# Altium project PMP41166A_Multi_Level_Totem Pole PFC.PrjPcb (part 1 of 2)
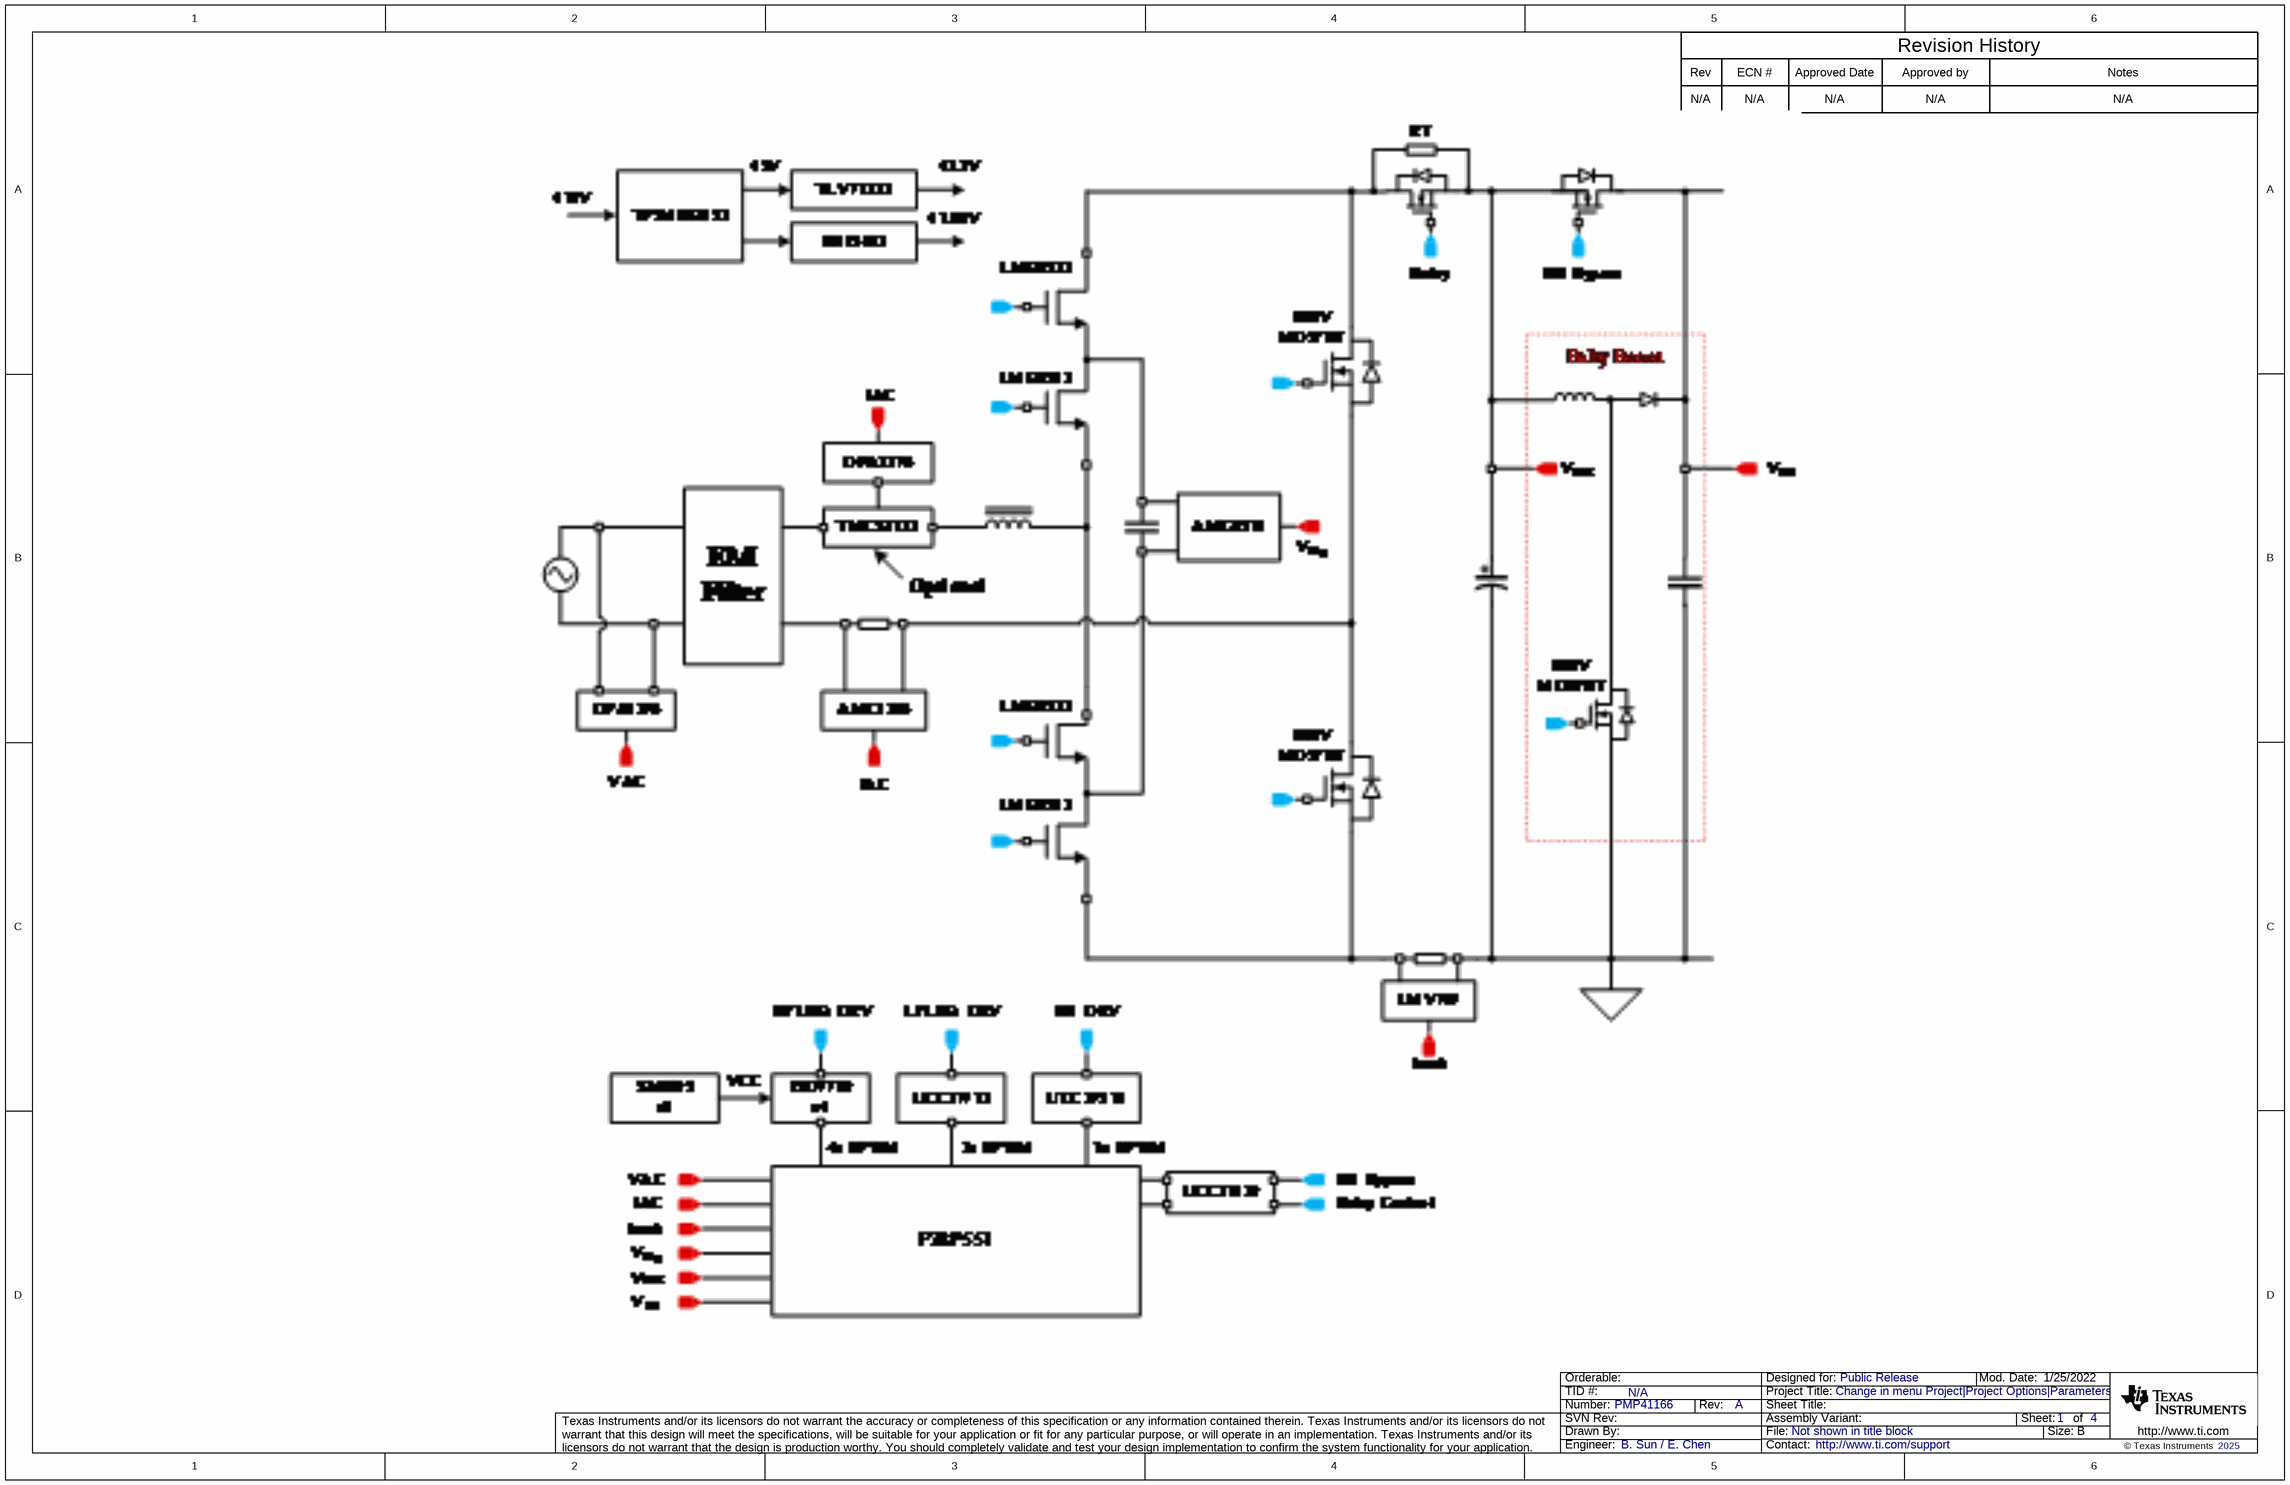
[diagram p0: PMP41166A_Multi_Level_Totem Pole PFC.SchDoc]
CopyrightYear: 2025; PCB_Layout: B. Sun / E. Chen; PCB_Rev: A; PRJ_Customer: Public Release; PRJ_Engineer: B. Sun / E. Chen; PRJ_Number: PMP41166; PRJ_Title: Change in menu Project|Project Options|Parameters; SCH_Rev: A; TechSupport: http://www.ti.com/support; TID: N/A
4 sheets, 262 parts. Net scope: flat (ports and power ports of the same name join across sheets).
Board file: PMP41166A_Multi_Level_Totem Pole PFC.PcbDoc
Sheets:
  PMP41166A_Multi_Level_Totem Pole PFC.SchDoc
  PMP41166A_Multi_Level_Totem Pole PFC_Main Board.SchDoc
  PMP41166A_Multi_Level_Totem Pole PFC_Control Card.SchDoc
  PMP41166A_Multi_Level_Totem Pole PFC_Hardware.SchDoc

## Sheet PMP41166A_Multi_Level_Totem Pole PFC.SchDoc
size 431 x 279 mm; Date: Not shown in title block; ApprovedBy: Not shown in title block; CheckedBy: Not shown in title block; Author: Not shown in title block; CompanyName: Not shown in title block; Engineer: Not shown in title block; Organization: Not shown in title block; Address1: Not shown in title block; Address2: Not shown in title block; Address3: Not shown in title block; Address4: Not shown in title block; DocumentNumber: 1; Revision: Use project parameter SCH_Rev; SheetNumber: 1; SheetTotal: 4; PageSetup: Record=PageOptions¦CenterHorizontal=True¦CenterVertical=True¦PrintScale=1.00¦XCorrection=1.00¦YCorrection=1.00¦PrintKind=0¦BorderSize=5000000¦LeftOffset=0¦BottomOffset=0¦Orientation=2¦PaperLength=1000¦PaperWidth=1000¦Scale=100¦PaperSource=15¦PrintQuality=600¦MediaType=1¦DitherType=10¦PaperKind=Letter¦PrintScaleMode=1

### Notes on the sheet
- Rev
- N/A
- ECN #
- Approved Date
- Approved by
- Revision History
- Notes

## Sheet PMP41166A_Multi_Level_Totem Pole PFC_Main Board.SchDoc
size A2; Date: Not shown in title block; ApprovedBy: Not shown in title block; CheckedBy: Not shown in title block; Author: Not shown in title block; CompanyName: Not shown in title block; Engineer: Not shown in title block; Organization: Not shown in title block; Address1: Not shown in title block; Address2: Not shown in title block; Address3: Not shown in title block; Address4: Not shown in title block; DocumentNumber: 1; Revision: Use project parameter SCH_Rev; SheetNumber: 2; SheetTotal: 4; PageSetup: Record=PageOptions¦CenterHorizontal=True¦CenterVertical=True¦PrintScale=0.69¦XCorrection=1.00¦YCorrection=1.00¦PrintKind=0¦BorderSize=5000000¦LeftOffset=0¦BottomOffset=0¦Orientation=2¦PaperLength=1000¦PaperWidth=1000¦Scale=100¦PaperSource=15¦PrintQuality=600¦MediaType=1¦DitherType=10¦PaperKind=Letter¦PrintScaleMode=1
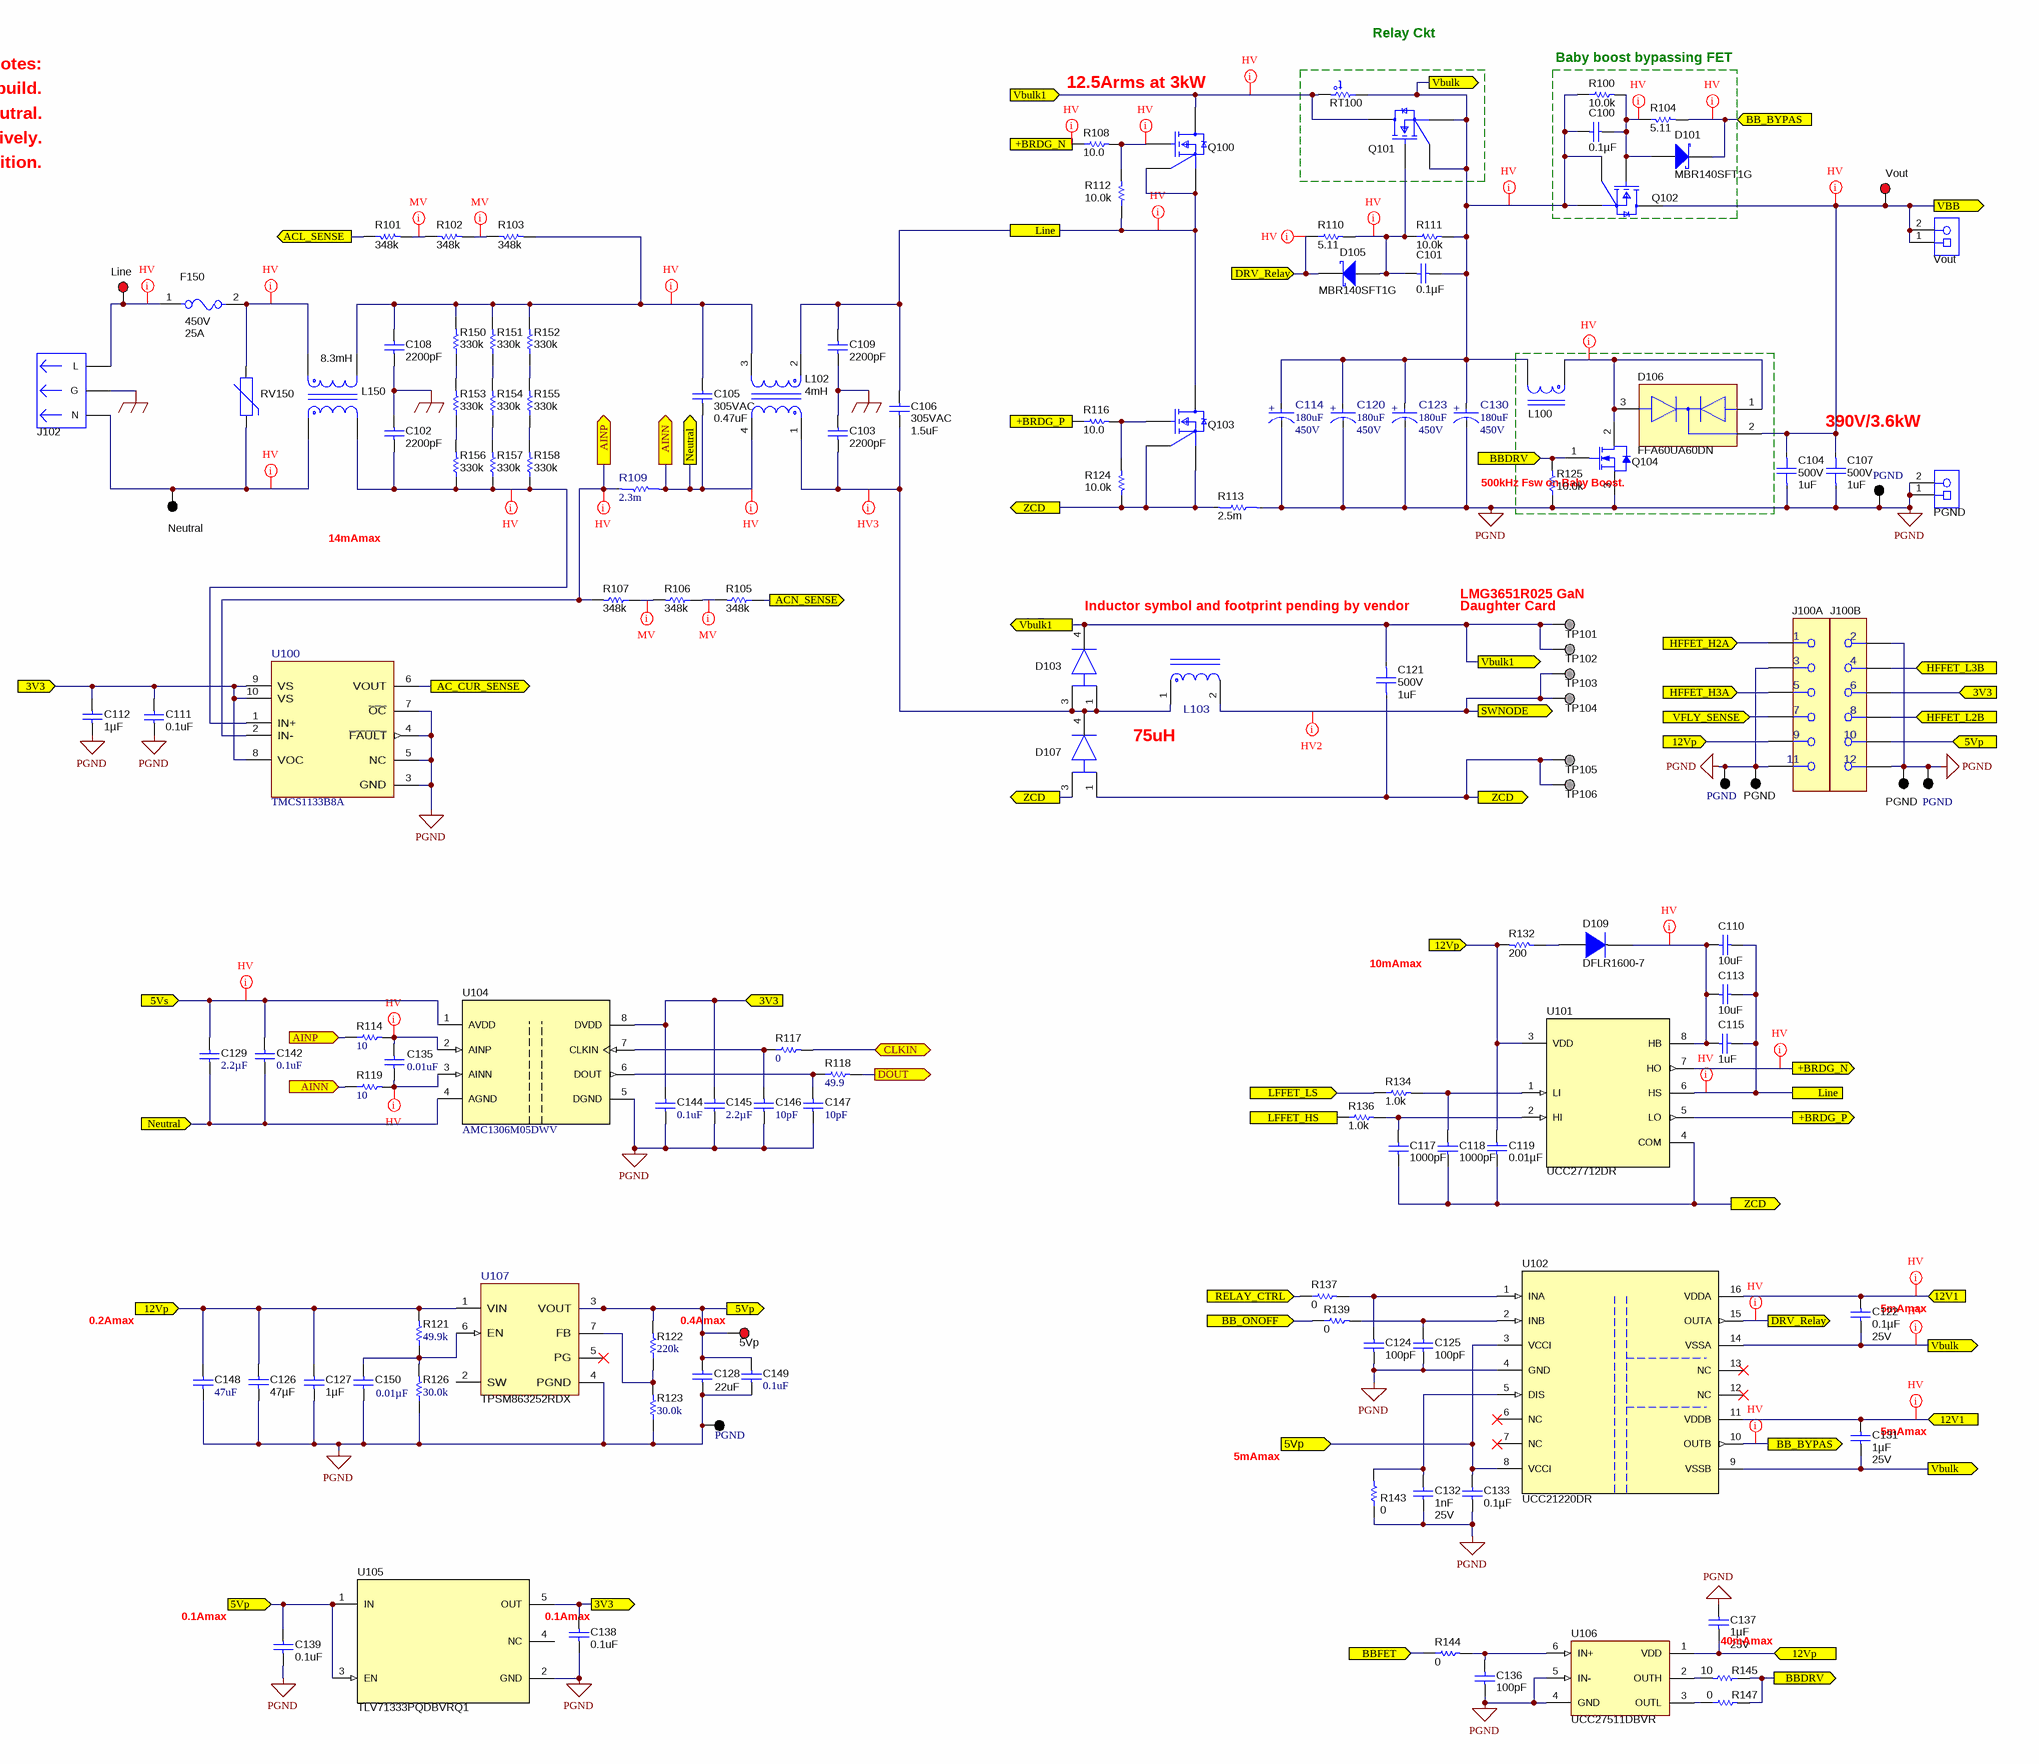
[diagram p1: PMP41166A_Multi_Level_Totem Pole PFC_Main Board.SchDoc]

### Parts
(Parts that share a designator on the sheet are numbered #1, #2 ... from top to bottom, then left to right.)
5Vp  5000  [Keystone5000]  (value not drawn)
C100  ValueDisplayed: 0.1µF  [0603]  (hidden comment: 06033C104JAT2A)
C101  ValueDisplayed: 0.1µF  [0603]  (hidden comment: 06033C104JAT2A)
C102  ValueDisplayed: 2200pF  [E_900x700x900]  (hidden comment: DE6E3KJ222MN3A)
C103  ValueDisplayed: 2200pF  [E_900x700x900]  (hidden comment: DE6E3KJ222MN3A)
C104  VDC_V: 500V  ValueDisplayed: 1uF  [FP-B58031U5105M062_SMD2-MFG]  (hidden comment: B58031U5105M062)
C105  Value2: 305VAC  ValueDisplayed: 0.47uF  [B32923_16.5mm_10.5]  (hidden comment: B32923H3474K000)
C106  Value2: 305VAC  ValueDisplayed: 1.5uF  [B32923_29.5mm]  (hidden comment: B32923H3155K000)
C107  VDC_V: 500V  ValueDisplayed: 1uF  [FP-B58031U5105M062_SMD2-MFG]  (hidden comment: B58031U5105M062)
C108  ValueDisplayed: 2200pF  [E_900x700x900]  (hidden comment: DE6E3KJ222MN3A)
C109  ValueDisplayed: 2200pF  [E_900x700x900]  (hidden comment: DE6E3KJ222MN3A)
C110  ValueDisplayed: 10uF  [0805_HV]  (hidden comment: 0805YD106MAT2A)
C111  ValueDisplayed: 0.1uF  [0402]  (hidden comment: GRM155R70J104KA01D)
C112  ValueDisplayed: 1µF  [0603]  (hidden comment: GRM185R60J105KE26D)
C113  ValueDisplayed: 10uF  [0805_HV]  (hidden comment: 0805YD106MAT2A)
C114  ValueDisplayed: 180uF  VDC_V: 450V  [FP-450HXW180MEFR16X50_RADIAL-MFG]  (hidden comment: 450HXW180MEFR16X50)
C115  ValueDisplayed: 1uF  [0603]  (hidden comment: C1608X7R1E105K080AB)
C117  ValueDisplayed: 1000pF  [0603]  (hidden comment: 06035A102KAT2A)
C118  ValueDisplayed: 1000pF  [0603]  (hidden comment: 06035A102KAT2A)
C119  ValueDisplayed: 0.01µF  [0603]  (hidden comment: C0603X103K5RACTU)
C120  ValueDisplayed: 180uF  VDC_V: 450V  [FP-450HXW180MEFR16X50_RADIAL-MFG]  (hidden comment: 450HXW180MEFR16X50)
C121  VDC_V: 500V  ValueDisplayed: 1uF  [FP-B58031U5105M062_SMD2-MFG]  (hidden comment: B58031U5105M062)
C122  ValueDisplayed: 0.1µF  Value2: 25V  [0603]  (hidden comment: 06033C104JAT2A)
C123  ValueDisplayed: 180uF  VDC_V: 450V  [FP-450HXW180MEFR16X50_RADIAL-MFG]  (hidden comment: 450HXW180MEFR16X50)
C124  ValueDisplayed: 100pF  [0402]  (hidden comment: 0402YC101KAT2A)
C125  ValueDisplayed: 100pF  [0402]  (hidden comment: 0402YC101KAT2A)
C126  ValueDisplayed: 47µF  [1210_270]  (hidden comment: GRM32ER61C476KE15L)
C127  Cap_F: 1µF  [0805_HV]  (hidden comment: C0805C105K3RACTU)
C128  ValueDisplayed: 22uF  [0805_HV]  (hidden comment: CL21A226KQQNNNE)
C129  Cap_F: 2.2µF  [0603]  (hidden comment: GCM188R70J225KE22D)
C130  ValueDisplayed: 180uF  VDC_V: 450V  [FP-450HXW180MEFR16X50_RADIAL-MFG]  (hidden comment: 450HXW180MEFR16X50)
C131  ValueDisplayed: 1µF  Value2: 25V  [1206]  (hidden comment: C3216X7R1E105K085AA)
C132  Cap_F: 1nF  VDC_V: 25V  [0603]  (hidden comment: GRM188R71E102KA01D)
C133  ValueDisplayed: 0.1µF  [0402]  (hidden comment: 0402YC104KAT2A)
C135  ValueDisplayed: 0.01uF  [0402]  (hidden comment: GRM155R60J103KA01D)
C136  ValueDisplayed: 100pF  [0402]  (hidden comment: 0402YC101KAT2A)
C137  ValueDisplayed: 1µF  Value2: 25V  [1206]  (hidden comment: C3216X7R1E105K085AA)
C138  ValueDisplayed: 0.1uF  [0402]  (hidden comment: GRM155R70J104KA01D)
C139  ValueDisplayed: 0.1uF  [0402]  (hidden comment: GRM155R70J104KA01D)
C142  ValueDisplayed: 0.1uF  [0402_065]  (hidden comment: 550L104KCAT)
C144  ValueDisplayed: 0.1uF  [0402_065]  (hidden comment: 550L104KCAT)
C145  Cap_F: 2.2µF  [0603]  (hidden comment: GCM188R70J225KE22D)
C146  ValueDisplayed: 10pF  [0402]  (hidden comment: C0402C100C8GACTU)
C147  ValueDisplayed: 10pF  [0402]  (hidden comment: C0402C100C8GACTU)
C148  ValueDisplayed: 47uF  [1210_270]  (hidden comment: GRM32ER61C476KE15L)
C149  ValueDisplayed: 0.1uF  [0402_065]  (hidden comment: 550L104KCAT)
C150  ValueDisplayed: 0.01µF  [0402]  (hidden comment: C0402C103K4RACTU)
D101  MBR140SFT1G  [SOD-123FL]
D103  VS-15EVL06-M3/I  [FP-VS-15AWL06FN-M3_D-PAK (TO-252AA)-MFG]  (value not drawn)
D105  MBR140SFT1G  [SOD-123FL]
D106  FFA60UA60DN  [FP-FFA60UA60DN_SC-65-MFG]
D107  VS-15EVL06-M3/I  [FP-VS-15AWL06FN-M3_D-PAK (TO-252AA)-MFG]  (value not drawn)
D109  DFLR1600-7  [PowerDI123]
F150  VDC_V: 450V  Fuse Current: 25A  [FP-0525025.MXEP_vm_AXIAL-MFG]  (hidden comment: 0525025.MXEP_vm)
J100  HLE-106-02-G-DV-BE-A  [FP-HLE-106-02-G-DV-BE-A_HDR12-MFG]  (value not drawn)  (parts A,B of 2)
J102  703W-00/54  [CONN_QUALTEK-703W-0054]  (value not drawn)
L100  PAL6598.223NL  [FP-PAL6281.104NL_PTH_20MM5_11MM0-MFG]  (value not drawn)
L102  Ind_H: 4mH  [FP-PAC6270NL_PTH_TRANSFORMER_30MM0_19MM0-MFG]  (hidden comment: PAC6596NL)
L103  PAL7753NL MX2  [FP-PAL7753NL MX2_PTH2-MFG]  (value not drawn)
L150  Ind_H: 8.3mH  [FP-PAC6280NL_PTH_25MM0_12MM5-MFG]  (hidden comment: PAC6597NL)
Line  L  [Keystone5000]  (value not drawn)
Neutral  N  [Keystone5001]  (value not drawn)
PGND#1  1715721  [PhoenixContact_1715721]  (value not drawn)
PGND#2  5  [Keystone5001]  (value not drawn)
PGND#3  5  [Keystone5001]  (value not drawn)
PGND#4  5001  [Keystone5001]  (value not drawn)
PGND#5  5001  [Keystone5001]  (value not drawn)
PGND#6  5  [Keystone5001]  (value not drawn)
PGND#7  5  [Keystone5001]  (value not drawn)
Q100  IPT60R022S7XTMA1  [FP-IPT60R080G7XTMA1_HSOF-8-MFG]  (value not drawn)
Q101  IPT60R022S7XTMA1  [FP-IPT60R080G7XTMA1_HSOF-8-MFG]  (value not drawn)
Q102  IPT60R022S7XTMA1  [FP-IPT60R080G7XTMA1_HSOF-8-MFG]  (value not drawn)
Q103  IPT60R022S7XTMA1  [FP-IPT60R080G7XTMA1_HSOF-8-MFG]  (value not drawn)
Q104  IPP60R060P7XKSA1  [TO-220AB]  (value not drawn)
R100  ValueDisplayed: 10.0k  [0603]  (hidden comment: CRCW060310K0FKEA)
R101  ValueDisplayed: 348k  [1206]  (hidden comment: RC1206FR-07348KL)
R102  ValueDisplayed: 348k  [1206]  (hidden comment: RC1206FR-07348KL)
R103  ValueDisplayed: 348k  [1206]  (hidden comment: RC1206FR-07348KL)
R104  ValueDisplayed: 5.11  [0603]  (hidden comment: CRCW06035R11FKEA)
R105  ValueDisplayed: 348k  [1206]  (hidden comment: RC1206FR-07348KL)
R106  ValueDisplayed: 348k  [1206]  (hidden comment: RC1206FR-07348KL)
R107  ValueDisplayed: 348k  [1206]  (hidden comment: RC1206FR-07348KL)
R108  ValueDisplayed: 10.0  [0603]  (hidden comment: CRCW060310R0FKEA)
R109  value 2.3m  [FP-CSS2H-2512K-2L30F_2512-MFG]  (hidden comment: CSS2H-2512K-2L30F)
R110  ValueDisplayed: 5.11  [1206]  (hidden comment: CRCW12065R11FKEA)
R111  ValueDisplayed: 10.0k  [0603]  (hidden comment: CRCW060310K0FKEA)
R112  ValueDisplayed: 10.0k  [0603]  (hidden comment: CRCW060310K0FKEA)
R113  value 2.5m  [FP-WSLP3921L1000FEA_3921-MFG]  (hidden comment: WSLP39212L500FEA)
R114  ValueDisplayed: 10  [0402]  (hidden comment: CRCW040210R0JNED)
R116  ValueDisplayed: 10.0  [0603]  (hidden comment: CRCW060310R0FKEA)
R117  ValueDisplayed: 0  [0402]  (hidden comment: CRCW04020000Z0ED)
R118  ValueDisplayed: 49.9  [0402]  (hidden comment: CRCW040249R9FKED)
R119  ValueDisplayed: 10  [0402]  (hidden comment: CRCW040210R0JNED)
R121  ValueDisplayed: 49.9k  [0402]  (hidden comment: CRCW040249K9FKED)
R122  ValueDisplayed: 220k  [0402]  (hidden comment: RC0402FR-07220KL)
R123  ValueDisplayed: 30.0k  [0402]  (hidden comment: CRCW040230K0FKED)
R124  ValueDisplayed: 10.0k  [0603]  (hidden comment: CRCW060310K0FKEA)
R125  ValueDisplayed: 10.0k  [0603]  (hidden comment: CRCW060310K0FKEA)
R126  ValueDisplayed: 30.0k  [0402]  (hidden comment: CRCW040230K0FKED)
R132  value 200  [0603]  (hidden comment: CRCW0603200RFKEA)
R134  value 1.0k  [0402]  (hidden comment: CRCW04021K00JNED)
R136  value 1.0k  [0402]  (hidden comment: CRCW04021K00JNED)
R137  ValueDisplayed: 0  [0402]  (hidden comment: CRCW04020000Z0ED)
R139  ValueDisplayed: 0  [0402]  (hidden comment: CRCW04020000Z0ED)
R143  ValueDisplayed: 0  [0603]  (hidden comment: CRCW06030000Z0EA)
R144  ValueDisplayed: 0  [0402]  (hidden comment: CRCW04020000Z0ED)
R145  ValueDisplayed: 10  [0603]  (hidden comment: CRCW060310R0JNEAHP)
R147  ValueDisplayed: 0  [0603]  (hidden comment: CRCW06030000Z0EA)
R150  ValueDisplayed: 330k  [1206]  (hidden comment: CRCW1206330KJNEA)
R151  ValueDisplayed: 330k  [1206]  (hidden comment: CRCW1206330KJNEA)
R152  ValueDisplayed: 330k  [1206]  (hidden comment: CRCW1206330KJNEA)
R153  ValueDisplayed: 330k  [1206]  (hidden comment: CRCW1206330KJNEA)
R154  ValueDisplayed: 330k  [1206]  (hidden comment: CRCW1206330KJNEA)
R155  ValueDisplayed: 330k  [1206]  (hidden comment: CRCW1206330KJNEA)
R156  ValueDisplayed: 330k  [1206]  (hidden comment: CRCW1206330KJNEA)
R157  ValueDisplayed: 330k  [1206]  (hidden comment: CRCW1206330KJNEA)
R158  ValueDisplayed: 330k  [1206]  (hidden comment: CRCW1206330KJNEA)
RT100  B59751B0120A070  [TDK_B751]  (value not drawn)
RV150  S10K275E2  [VAR_S10K275E2]  (value not drawn)
TP101  Suggest using a net name here  [Mill-Max_0312-0-15-15-34-27-10-0]  (value not drawn)
TP102  Suggest using a net name here  [Mill-Max_0312-0-15-15-34-27-10-0]  (value not drawn)
TP103  Suggest using a net name here  [Mill-Max_0312-0-15-15-34-27-10-0]  (value not drawn)
TP104  Suggest using a net name here  [Mill-Max_0312-0-15-15-34-27-10-0]  (value not drawn)
TP105  Suggest using a net name here  [Mill-Max_0312-0-15-15-34-27-10-0]  (value not drawn)
TP106  Suggest using a net name here  [Mill-Max_0312-0-15-15-34-27-10-0]  (value not drawn)
U100  TMCS1133B8A  [DVG0010A-MFG]
U101  UCC27712DR  [D0008A_N]
U102  UCC21220DR  [D0016B]
U104  AMC1306M05DWV  [DWV0008A]
U105  TLV71333PQDBVRQ1  [DBV0005A_N]
U106  UCC27511DBVR  [DBV0006A_N]
U107  TPSM863252RDX  [RDX0007A-MFG]
Vout#1  L  [Keystone5000]  (value not drawn)
Vout#2  1715721  [PhoenixContact_1715721]  (value not drawn)

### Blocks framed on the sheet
Baby boost bypassing FET: C100 D101 Q102 R100 R104
500kHz Fsw on Baby Boost.: D106 L100 Q104 R125

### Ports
3V3 (in), 3V3 (out), 5Vp (in), 5Vp (out), 5Vs (in), 12V1 (in), 12Vp (in), +BRDG_N (in), +BRDG_N (out), +BRDG_P (in), +BRDG_P (out), AC_CUR_SENSE (out), ACL_SENSE (out), ACN_SENSE (out), AINN (in), AINN (out), AINP (in), AINP (out), BB_BYPAS (in), BB_BYPAS (out), BB_ONOFF (in), BBDRV (in), BBDRV (out), BBFET (in), CLKIN (bidir), DOUT (out), DRV_Relay (in), DRV_Relay (out), HFFET_H2A (in), HFFET_H3A (in), HFFET_L2B (in), HFFET_L3B (in), LFFET_HS (in), LFFET_LS (in), Line, Neutral (in), Neutral (out), RELAY_CTRL (in), SWNODE (out), VBB (out), Vbulk1 (in), Vbulk1 (out), Vbulk (out), VFLY_SENSE (in), ZCD (out)

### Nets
PE: C102.2 C103.2 C108.1 C109.1 J102.3(G)
PGND: C104.1 C107.1 C111.2 C112.2 C114.1(CATHODE) C120.1(CATHODE) C123.1(CATHODE) C124.2 C125.2 C126.1 C127.2 C128.2 C130.1(CATHODE) C132.2 C133.2 C136.2 C137.2 C138.2 C139.2 C144.2 C145.2 C146.2 C147.2 C148.2 C149.2 C150.2 J100.2 J100.3 J100.11 J100.12 PGND#1.1 PGND#1.2 PGND#2.1 PGND#3.1 PGND#4.1 PGND#5.1 PGND#6.1 PGND#7.1 Q104.3(S) R113.1 R123.1 R125.1 R126.1 R143.1 U100.3(GND) U100.4(~{FAULT}) U100.5(NC) U100.7(~{OC}) U102.4(GND) U104.5(DGND) U105.2(GND) U106.4(GND) U106.5(IN-) U107.4(PGND)
3V3: C111.1 C112.1 C138.1 C144.1 C145.1 J100.6 U100.8(VOC) U100.9(VS) U100.10(VS) U104.8(DVDD) U105.5(OUT) ; port 3V3
5Vp: 5Vp.1 C128.1 C133.1 C139.1 C149.1 J100.10 R122.2 U102.3(VCCI) U102.8(VCCI) U105.1(IN) U105.3(EN) U107.3(VOUT) ; port 5Vp
5Vs: C129.1 C142.1 U104.1(AVDD) ; port 5Vs
12V1: C122.2 C131.1 U102.11(VDDB) U102.16(VDDA) ; port 12V1
12Vp: C119.1 C126.2 C127.1 C137.1 C148.1 J100.9 R121.2 R132.2 U101.3(VDD) U106.1(VDD) U107.1(VIN) ; port 12Vp
+BRDG_N: R108.1 U101.7(HO) ; port +BRDG_N
+BRDG_P: R116.1 U101.5(LO) ; port +BRDG_P
AC_CUR_SENSE: U100.6(VOUT) ; port AC_CUR_SENSE
ACL_SENSE: R101.1 ; port ACL_SENSE
ACN_SENSE: R105.1 ; port ACN_SENSE
AINN: C105.1 C129.2 C142.2 L102.4 R109.2 R119.1 U104.4(AGND) ; port AINN, port Neutral
AINP: R107.2 R109.1 R114.1 U100.2(IN-) ; port AINP
BB_BYPAS: D101.1(K) R104.2 U102.10(OUTB) ; port BB_BYPAS
BB_ONOFF: R139.1 ; port BB_ONOFF
BBDRV: Q104.1(G) R125.2 R145.1 R147.2 ; port BBDRV
BBFET: R144.1 ; port BBFET
CLKIN: R117.2 ; port CLKIN
DOUT: R118.2 ; port DOUT
DRV_Relay: D105.1(K) R110.1 U102.15(OUTA) ; port DRV_Relay
HFFET_H2A: J100.1 ; port HFFET_H2A
HFFET_H3A: J100.5 ; port HFFET_H3A
HFFET_L2B: J100.8 ; port HFFET_L2B
HFFET_L3B: J100.4 ; port HFFET_L3B
LFFET_HS: R136.1 ; port LFFET_HS
LFFET_LS: R134.1 ; port LFFET_LS
Line: C106.2 C109.2 C110.2 C113.2 C115.1 L102.2 Q100.2(Driver_Source) Q100.3-4-5-6-7-8(Source) Q103.9(Drain) R112.1 U101.6(HS) ; port Line
RELAY_CTRL: R137.1 ; port RELAY_CTRL
SWNODE: L103.2 TP103.1 TP104.1 ; port SWNODE
VBB: C104.2 C107.2 D106.2(COMMON_CATHODE) Q102.9(Drain) Vout#1.1 Vout#2.1 Vout#2.2 ; port VBB
Vbulk: C100.2 C101.1 C114.2(ANODE) C120.2(ANODE) C122.1 C123.2(ANODE) C130.2(ANODE) C131.2 L100.2(F) Q101.2(Driver_Source) Q101.3-4-5-6-7-8(Source) Q102.2(Driver_Source) Q102.3-4-5-6-7-8(Source) R100.1 R111.2 RT100.1 U102.9(VSSB) U102.14(VSSA) ; port Vbulk
Vbulk1: C121.2 D103.4(Cathode) Q100.9(Drain) Q101.9(Drain) RT100.2 TP101.1 TP102.1 ; port Vbulk1
VFLY_SENSE: J100.7 ; port VFLY_SENSE
ZCD: C117.2 C118.2 C119.2 C121.1 D107.1(Anode) D107.3(Anode) Q103.2(Driver_Source) Q103.3-4-5-6-7-8(Source) R113.2 R124.1 TP105.1 TP106.1 U101.4(COM) ; port ZCD
NetC100_1: C100.1 D101.2(A) Q102.1(Gate) R100.2 R104.1
NetC101_2: C101.2 D105.2(A) Q101.1(Gate) R110.2 R111.1
NetC102_1: C102.1 L150.4 R156.1 R157.1 R158.1 U100.1(IN+)
NetC103_1: C103.1 C106.1 D103.1(Anode) D103.3(Anode) D107.4(Cathode) L102.1 L103.1
NetC105_2: C105.2 C108.2 L102.3 L150.3 R103.2 R150.2 R151.2 R152.2
NetC110_1: C110.1 C113.1 C115.2 D109.1(K) U101.8(HB)
NetC117_1: C117.1 R136.2 U101.2(HI)
NetC118_1: C118.1 R134.2 U101.1(LI)
NetC124_1: C124.1 R137.2 U102.1(INA)
NetC125_1: C125.1 R139.2 U102.2(INB)
NetC132_1: C132.1 R143.2 U102.5(DIS)
NetC135_1: C135.1 R114.2 U104.2(AINP)
NetC135_2: C135.2 R119.2 U104.3(AINN)
NetC136_1: C136.1 R144.2 U106.6(IN+)
NetC146_1: C146.1 R117.1 U104.7(CLKIN)
NetC147_1: C147.1 R118.1 U104.6(DOUT)
NetC150_1: C150.1 R121.1 R126.2 U107.6(EN)
NetD106_1: D106.1(1_ANODE) D106.3(2_ANODE) L100.1(S) Q104.2(D)
NetD109_2: D109.2(A) R132.1
NetF150_1: F150.1 J102.1(L) Line.1
NetF150_2: F150.2 L150.2 RV150.1
NetJ102_2: J102.2(N) L150.1 Neutral.1 RV150.2
NetQ100_1: Q100.1(Gate) R108.2 R112.2
NetQ103_1: Q103.1(Gate) R116.2 R124.2
NetR101_2: R101.2 R102.1
NetR102_2: R102.2 R103.1
NetR105_2: R105.2 R106.1
NetR106_2: R106.2 R107.1
NetR122_1: R122.1 R123.2 U107.7(FB)
NetR145_2: R145.2 U106.2(OUTH)
NetR147_1: R147.1 U106.3(OUTL)
NetR150_1: R150.1 R153.2
NetR151_1: R151.1 R154.2
NetR152_1: R152.1 R155.2
NetR153_1: R153.1 R156.2
NetR154_1: R154.1 R157.2
NetR155_1: R155.1 R158.2

Not connected (* = marked no-connect by the designer): U102 6(NC)* 7(NC)* 12(NC)* 13(NC)*; U105 4(NC); U107 2(SW) 5(PG)*

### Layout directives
net class HV: 5Vs, 12V1, +BRDG_N, AINN, AINP, BB_BYPAS, DRV_Relay, Line, NetC100_1, NetC101_2, NetC102_1, NetC105_2, NetC110_1, NetC135_1, NetC135_2, NetD106_1, NetF150_1, NetF150_2, NetJ102_2, NetQ100_1, VBB, Vbulk, Vbulk1
net class MV: NetR101_2, NetR102_2, NetR105_2, NetR106_2
net class HV3: NetC103_1
net class HV2: SWNODE

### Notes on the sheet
- Relay Ckt
- Notes:
- 1. Need to check part availability when request to build.
- 12.5Arms at 3kW
- 2. This board uses boot strap gate driver for LF FETs, does not support negative DC input on Neutral.
- 3. 4x 180uF bulk cap is applied: C123 and C130 to be placed on top of C114 and C120, respectively.
- 4. C114, C120, C123, C130 in laid down position.
- 390V/3.6kW
- 14mAmax
- (near TP101) LMG3651R025 GaN
- Inductor symbol and footprint pending by vendor
- (near TP101) Daughter Card
- (near L103) 75uH
- (near R132) 10mAmax
- 0.2Amax
- (near 5Vp) 0.4Amax
- 5mAmax
- (near C139) 0.1Amax
- (near C138) 0.1Amax
- 40mAmax

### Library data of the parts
5Vp = 5000: Test Point, Miniature, Red, TH; Manufacturer: Keystone; CompType: Test Point Loop; ContactFinish: Silver; Green_Lifecycle: Active; Green_REACh: Passed
C100 C101 C122 = 06033C104JAT2A: CAP, CERM, 0.1uF, 25V, +/-5%, X7R, 0603; Manufacturer: AVX; Polarized: N; CompType: Capacitor; U/M: EA; Cap_F: 0.0000001; Tolerance_%: 5; ESR_Ohm: 0.05; Value1: 0.05 ohm; VDC_V: 25; TaMin_C: -55; TaMax_C: 125
C102 C103 C108 C109 = DE6E3KJ222MN3A: CAP, CERM, 2200 pF, 300 V, +/- 20%, E, TH, 2- Leads, Body 9x7mm, Pin Spacing 7.5mm; Manufacturer: MuRata; Polarized: N; CompType: Capacitor; Value: 2200pF; U/M: EA; Cap_F: 0.0000000022; Tolerance_%: 20; Value1: Unknown; VDC_V: 300; Value2: 300V; TaMin_C: -40; TaMax_C: 125; Cap_Case: 9x7x9mm; SizeArea_mm2: 63; SizeAreaWB_mm2: 99; SizeX_mm: 9; SizeY_mm: 7; SizeZ_mm: 12; AEC Category: Q200
C104 C107 C121 = CMP-0091050-1: TDK 1µF Multilayer Ceramic Capacitor MLCC 500V dc ±20% SMD; AEC Grade: Grade 0; AEC Qualified: Yes; SizeZ_mm: 4.5mm
C105 = CMP-0012429-3: CAP FILM 0.47UF 10% 630VDC RAD; Manufacturer: TDK; Polarized: N; SizeAreaWB_mm2: 356.25; Value1: Unknown; TaMax_C: 110°C; Tolerance_%: 20%; SizeZ_mm: 16.5; SizeX_mm: 26.5; SizeY_mm: 10.5; SizeArea_mm2: 278.25; CompType: Capacitor; Cap_F: 470nF; VDC_V: 630V; AEC Category: Q200
C106 = CMP-0012424-1: CAP FILM 1.5UF 10% 630VDC RADIAL; Manufacturer: TDK; Polarized: N; SizeAreaWB_mm2: 470.25; Value1: Unknown; U/M: EA; TaMax_C: 110°C; Tolerance_%: 20%; SizeZ_mm: 29.5; SizeX_mm: 26.5; SizeY_mm: 14.5; SizeArea_mm2: 384.25; CompType: Capacitor; Cap_F: 1.5µF; VDC_V: 630V; AEC Category: Q200
C110 C113 = 0805YD106MAT2A: CAP, CERM, 10uF, 16V, +/-20%, X5R, 0805; Manufacturer: AVX; Polarized: N; CompType: Capacitor; U/M: EA; Cap_F: 0.00001; Tolerance_%: 20; Value1: Unknown; VDC_V: 16; TaMin_C: -55; TaMax_C: 85; Cap_Case: 0805
C111 C138 C139 = GRM155R70J104KA01D: CAP, CERM, 0.1uF, 6.3V, +/-10%, X7R, 0402; Manufacturer: MuRata; Polarized: N; CompType: Capacitor; U/M: EA; Cap_F: 0.0000001; Tolerance_%: 10; Value1: Unknown; VDC_V: 6.3; TaMin_C: -55; TaMax_C: 125
C112 = GRM185R60J105KE26D: CAP, CERM, 1uF, 6.3V, +/-10%, X5R, 0603; Manufacturer: MuRata; Polarized: N; CompType: Capacitor; U/M: EA; Cap_F: 0.000001; Tolerance_%: 10; Value1: Unknown; VDC_V: 6.3; TaMin_C: -55; TaMax_C: 85
C114 C120 C123 C130 = CMP-0098127-1: 180 µF 450 V Aluminum Electrolytic Capacitors Radial, Can 3000 Hrs @ 105°C; Manufacturer: Rubycon; Tolerance_%: 20%; SizeZ_mm: 52mm; Life: 3000Hours; Dissipation Factor: 25%; AEC Qualified: No; Cap_F: 180µF; Value: 180µF; Leakage Current: 853.8uA; IRMS_A: 1.15A
C115 = C1608X7R1E105K080AB: CAP, CERM, 1uF, 25V, +/-10%, X7R, 0603; Manufacturer: TDK; Polarized: N; CompType: Capacitor; U/M: EA; Cap_F: 0.000001; Tolerance_%: 10; Value1: Unknown; VDC_V: 25; TaMin_C: -55; TaMax_C: 125
C117 C118 = 06035A102KAT2A: CAP, CERM, 1000 pF, 50 V, +/- 10%, C0G/NP0, 0603; Manufacturer: AVX; Polarized: N; CompType: Capacitor; Value: 1000pF; U/M: EA; Cap_F: 0.000000001; Tolerance_%: 10; ESR_ohm: 0.048; Value1: 0.048 ohm; VDC_V: 50; Value2: 50V; TaMin_C: -55; TaMax_C: 125; SizeArea_mm2: 1.28; SizeAreaWB_mm2: 4.68; SizeX_mm: 1.6; SizeY_mm: 0.8; SizeZ_mm: 1; AEC Category: Q200
C119 = C0603X103K5RACTU: CAP, CERM, 0.01uF, 50V, +/-10%, X7R, 0603; Manufacturer: Kemet; Polarized: N; CompType: Capacitor; U/M: EA; Cap_F: 0.00000001; Tolerance_%: 10; Value1: Unknown; VDC_V: 50; TaMin_C: -55; TaMax_C: 125
C124 C125 C136 = 0402YC101KAT2A: CAP, CERM, 100 pF, 16 V,+/- 10%, X7R, 0402; Manufacturer: AVX; Polarized: N; CompType: Capacitor; Value: 100pF; U/M: EA; Cap_F: 0.0000000001; Tolerance_%: 10; VDC_V: 16; Value2: 16V; TaMin_C: -55; TaMax_C: 125; SizeArea_mm2: 0.5; SizeAreaWB_mm2: 3; SizeX_mm: 1; SizeZ_mm: 0.6; AEC Category: Q200
C126 = GRM32ER61C476KE15L: CAP, CERM, 47 µF, 16 V, +/- 10%, X5R, 1210; Manufacturer: MuRata; Polarized: N; CompType: Capacitor; Value: 47uF; U/M: EA; Cap_F: 0.000047; Tolerance_%: 10; Value1: Unknown; VDC_V: 16; TaMin_C: -55; TaMax_C: 85; Cap_Case: 1210; SizeArea_mm2: 8; SizeAreaWB_mm2: 14.7; SizeX_mm: 3.2; SizeY_mm: 2.5; SizeZ_mm: 2.7; AEC Category: Q200
C127 = CMP-0007728-2: CAP, CERM, 1 uF, 25 V, +/- 10%, X7R, 0805; Manufacturer: Kemet; TaMin_C: -55°C; Polarized: N; SizeAreaWB_mm2: 6.75; Value1: Unknown; U/M: EA; Value: 1uF; TaMax_C: 125°C; SizeZ_mm: 1.45; SizeX_mm: 2; SizeY_mm: 1.25; Cap_Case: 0805; Value2: 25V; SizeArea_mm2: 2.5; AEC Category: Q200
C128 = CMP-0007989-2: CAP, CERM, 22 uF, 6.3 V, +/- 10%, X5R, 0805; Manufacturer: Samsung Electro-Mechanics; TaMin_C: -55°C; Polarized: N; SizeAreaWB_mm2: 6.75; Value1: Unknown; U/M: EA; Value: 22uF; TaMax_C: 85°C; SizeZ_mm: 1.45; SizeX_mm: 2; SizeY_mm: 1.25; Cap_Case: 0805; Value2: 6.3V; SizeArea_mm2: 2.5; Cap_F: 22µF; AEC Category: Q200
C129 C145 = CMP-0007134-5: CAP, CERM, 2.2 uF, 6.3 V, +/- 10%, X7R, AEC-Q200 Grade 1, 0603; Manufacturer: MuRata; TaMin_C: -55°C; Polarized: N; SizeAreaWB_mm2: 4.68; Value1: Unknown; U/M: EA; Value: 2.2uF; TaMax_C: 125°C; SizeZ_mm: 1; SizeX_mm: 1.6; SizeY_mm: 0.8; Value2: 6.3V; SizeArea_mm2: 1.28; AEC Qualified: Y; AEC Category: Q200
C131 C137 = C3216X7R1E105K085AA: CAP, CERM, 1 µF, 25 V,+/- 10%, X7R, 1206; Manufacturer: TDK; Polarized: N; CompType: Capacitor; Value: 1uF; U/M: EA; Cap_F: 0.000001; Tolerance_%: 10; ESR_ohm: 0.01; Value1: 0.01 ohm; VDC_V: 25; TaMin_C: -55; TaMax_C: 125; SizeArea_mm2: 5.12; SizeAreaWB_mm2: 10.92; SizeX_mm: 3.2; SizeY_mm: 1.6; SizeZ_mm: 1.35; AEC Category: Q200; Green_Lifecycle: NRND; Green_REACh: Passed
C132 = CMP-0007402-1: CAP, CERM, 1000 pF, 25 V, +/- 10%, X7R, 0603; Manufacturer: MuRata; TaMin_C: -55°C; Polarized: N; SizeAreaWB_mm2: 4.68; Value1: Unknown; U/M: EA; Value: 1000pF; TaMax_C: 125°C; SizeZ_mm: 1; SizeX_mm: 1.6; SizeY_mm: 0.8; SizeArea_mm2: 1.28; AEC Category: Q200
C133 = 0402YC104KAT2A: CAP, CERM, 0.1 µF, 16 V,+/- 10%, X7R, 0402; Manufacturer: AVX; Polarized: N; CompType: Capacitor; Value: 0.1uF; U/M: EA; Cap_F: 0.0000001; Tolerance_%: 10; VDC_V: 16; Value2: 16V; TaMin_C: -55; TaMax_C: 125; SizeArea_mm2: 0.5; SizeAreaWB_mm2: 3; SizeX_mm: 1; SizeZ_mm: 0.6; AEC Category: Q200; Green_Lifecycle: Active; Green_REACh: Passed
C135 = CMP-0006530-2: CAP, CERM, 0.01 uF, 6.3 V, +/- 10%, X5R, 0402; Manufacturer: MuRata; TaMin_C: -55°C; Polarized: N; SizeAreaWB_mm2: 3; Value1: Unknown; U/M: EA; Value: 0.01uF; TaMax_C: 85°C; SizeZ_mm: 0.6; SizeX_mm: 1; SizeY_mm: 0.5; Value2: 6.3V; Cap_F: 10nF; AEC Category: Q200
C142 C144 C149 = CMP-0006211-1: CAP, CERM, 0.1 uF, 16 V, +/- 10%, Unknown, 0402; Manufacturer: AT Ceramics; TaMin_C: -55°C; Polarized: N; SizeAreaWB_mm2: 3; U/M: EA; Value: 0.1uF; TaMax_C: 125°C; SizeZ_mm: 0.65; SizeX_mm: 1; SizeY_mm: 0.5; Cap_Case: 0402; Value2: 16V; Cap_F: 100nF; AEC Category: Q200
C146 C147 = CMP-0064914-1: CAP, CERM, 10 pF, 10 V,+/- 2.5%, C0G/NP0, 0402; Manufacturer: Kemet; TaMin_C: -55°C; Polarized: N; SizeAreaWB_mm2: 3; Value1: Unknown; U/M: EA; Value: 10pF; TaMax_C: 125°C; SizeZ_mm: 0.6; SizeX_mm: 1; SizeY_mm: 0.5; Value2: 10V; AEC Category: Q200
C148 = CMP-0009211-1: CAP, CERM, 47 uF, 16 V, +/- 10%, X5R, 1210; Manufacturer: MuRata; TaMin_C: -55°C; Polarized: N; SizeAreaWB_mm2: 14.7; Value1: Unknown; U/M: EA; Value: 47uF; TaMax_C: 85°C; SizeZ_mm: 2.7; SizeX_mm: 3.2; SizeY_mm: 2.5; Cap_Case: 1210; Value2: 16V; SizeArea_mm2: 8; Cap_F: 47µF; AEC Category: Q200
C150 = CMP-0078218-1: CAP, CERM, 0.01 µF, 16 V,+/- 10%, X7R, 0402; Manufacturer: Kemet; TaMin_C: -55°C; Polarized: N; Green_Lifecycle: Active; SizeAreaWB_mm2: 3; Green_REACh: Passed; U/M: EA; Value: 0.01uF; TaMax_C: 125°C; SizeZ_mm: 0.6; SizeX_mm: 1; SizeY_mm: 0.5; Value2: 16V; Cap_F: 10nF; AEC Category: Q200
D101 D105 = CMP-0028548-2: Diode, Schottky, 40 V, 1 A, SOD-123FL; Manufacturer: ON Semiconductor; SizeZ_mm: 0.98; Vf_V: 5.5dV; AEC Category: Q101; Green_REACh: Passed; SizeArea_mm2: 5.94; Vr_V: 40V; TJmax_C: 125°C; RJC_CperW: 26; Value1: 1A; SizeY_mm: 1.65; SizeX_mm: 3.6; Value: 40V; Value2: 0.55V; SizeAreaWB_mm2: 12.19; Green_Lifecycle: Active
D103 D107 = CMP-0086603-1: DIODE GEN PURPOSE 600V SLIMDPAK; Manufacturer: Vishay; TJmax_C: 175°C; SizeZ_mm: 2.52mm; AEC Qualified: No
D106 = CMP-0090872-1: Diode Array 1 Pair Common Cathode Standard 600V 30A Through Hole TO-3P-3, SC-65-3; Manufacturer: ON Semiconductor; Peak Reverse Current: 100uA; SizeZ_mm: 23.8mm; AEC Qualified: No; TJmax_C: 175°C; Max Surge Forward Current: 180A; Standoff Height: 3.3mm
D109 = CMP-0076978-2: Diode, Standard Recovery Rectifier, 600 V, 1 A, PowerDI123; Manufacturer: Diodes Inc.; AEC Category: Q101; SizeAreaWB_mm2: 13.066; SizeY_mm: 1.78; Value2: 1.1V; TJmax_C: 150°C; Green_Lifecycle: Not Set; Value1: 1A; Value: 600V; SizeZ_mm: 0.98; SizeX_mm: 3.7; SizeArea_mm2: 6.586; Green_REACh: Incomplete
F150 = CMP-4956-0000-1: 25A AC 450V DC Fuse Cartridge, Ceramic Through Hole 3AB, 3AG, 1/4" x 1-1/4" (Axial); Manufacturer: Littelfuse; AEC Grade: NA; Fuse Interrupt Dc Current: 10000A; AEC Qualified: No; Res_ohm: 3.8mΩ; MeltingTyp: 320A2Sec; Interrupt_DC: 10kA
J100 = CMP-0089984-1: 12 Position Receptacle, Bottom Entry Connector  Surface Mount; Manufacturer: Samtec; Current_A: 4.1A; Conn Orientation: Vertical; DUT-Pitch_mm: 2.54mm; Conn Gender: Female; SizeZ_mm: 3.79mm; Is Female: yes; AEC Qualified: No; ContactFinish: Gold,Nickel; Voltage_V: 400V; Row_Count: 2
J102 = 703W-00/54: AC Receptacle, 10A 250VAC; Manufacturer: Qualtek Electronics Corporation; SymbolCreator: a0799628; CompType: Connector; U/M: EA
L100 = CMP-0091020-1: Inductor Buck/Boost, Toroid, TH, 22uH 15% 8A; Manufacturer: Pulse Electronics; DCR_ohm: 1.08d; AEC Qualified: No; SizeZ_mm: 22.5mm; Test Frequency: 100kHz; Ind_H: 100µH
L102 = CMP-0091106-1: IND, CUR-SENSE, 4MH, 20A, TOR, TH; Manufacturer: Pulse Electronics; DCR_ohm: 6m; Voltage_Isolation_Vrms: 1500VDC; AEC Qualified: No; SizeZ_mm: 32mm; Rsec1_ohm: 6mΩ; Ns1toNp: 1:1
L103 = CMP-0126880-1: INDUCTOR ER20, 75uH; Manufacturer: YAGEO; AEC Qualified: No; DCR_ohm: 19m; Ind_H: 75µH; SizeZ_mm: 25mm; Test Frequency: 100kHz; Tolerance_%: 12%
L150 = CMP-0091125-1: INDUCTOR CUR-SENSE 8.3mH TOR TH; Manufacturer: Pulse Electronics; Tolerance_%: 30%; AEC Qualified: No; SizeZ_mm: 24.5mm; Test Frequency: 10kHz; DCR_ohm: 0.012
Line Vout#1 = 5000: Test Point, Miniature, Red, TH; Manufacturer: Keystone; CompType: Test Point Loop; U/M: EA
Neutral = 5001: Test Point, Miniature, Black, TH; Manufacturer: Keystone; CompType: Test Point Loop; U/M: EA
PGND#1 Vout#2 = CMP-0055471-1: Terminal Block, 5.08 mm, 2x1, TH; Manufacturer: Phoenix Contact; Cert_VDE: Y; CNHeader: FALSE; Current_A: 17.5A; Green_Lifecycle: Not Set; Gender: Female; Cert_CULUS: N; Green_REACh: Incomplete; Voltage_V: 400V; Row_Count: 1; Pitch_mm: 5.08; ContactFinish: Tin; CT: TRUE
PGND#2 PGND#3 PGND#6 PGND#7 = CMP-0055138-1: Test Point, Miniature, Black, TH; Manufacturer: Keystone; CNHeader: FALSE; Green_Lifecycle: Active; Green_REACh: Passed; ContactFinish: Silver; CT: TRUE
PGND#4 PGND#5 = 5001: Test Point, Miniature, Black, TH; Manufacturer: Keystone; CompType: Test Point Loop; ContactFinish: Silver; Green_Lifecycle: Active; Green_REACh: Passed
Q100-Q103 = CMP-0086487-1: N-Channel 600V 23A (Tc) 390W (Tc) Surface Mount PG-HSOF-8-2; Manufacturer: Infineon; VdsMax_V: 650V; IdsMax_A: 29A; Vgs_V: 20V; AEC Qualified: No; ChMode: False; SizeZ_mm: 2.4mm
Q104 = CMP-0001223-3: MOSFET N-CH 600V 48A TO220-3; Alternate Manufacturer: None; Manufacturer: Infineon Technologies; ChType: N; AEC Category: Q101; U/M: EA
R100 R111 R112 R124 R125 = CRCW060310K0FKEA: RES, 10.0 k, 1%, 0.1 W, 0603; Manufacturer: Vishay-Dale; CompType: Resistor; Value: 10.0k; Res_ohm: 10000; Value_Code: 10k0; Tolerance_%: 1; Power_W: 0.1; Value2: 0.1W; VDC_V: 75; TempCo: 100 ppm/C; SizeArea_mm2: 1.28; SizeX_mm: 1.6; SizeY_mm: 0.8; EIA_Code: E96; U/M: EA; AEC Category: Q200; Green_Lifecycle: Active; Green_REACh: Passed
R101-R103 R105-R107 = CMP-0018215-2: RES, 348 k, 1%, 0.25 W, 1206; Manufacturer: Yageo America; Power_W: 250mW; TempCo: 100 ppm/C; U/M: EA; Value: 348k; EIA_Code: E96; SizeX_mm: 3.2; SizeY_mm: 1.6; SizeZ_mm: 1.35; Value2: 0.25W; SizeArea_mm2: 5.12; VDC_V: 200V; AEC Category: Q200
R104 = CRCW06035R11FKEA: RES, 5.11, 1%, 0.1 W, 0603; Manufacturer: Vishay-Dale; CompType: Resistor; Value: 5.11; Value_Code: 5R11; Tolerance_%: 1; Power_W: 0.1; Value2: 0.1W; VDC_V: 75; TempCo: 100 ppm/C; SizeArea_mm2: 1.28; SizeX_mm: 1.6; SizeY_mm: 0.8; EIA_Code: E96; U/M: EA; AEC Category: Q200; Green_Lifecycle: Active; Green_REACh: Passed
R108 R116 = CRCW060310R0FKEA: RES, 10.0, 1%, 0.1 W, 0603; Manufacturer: Vishay-Dale; CompType: Resistor; Value: 10.0; Res_ohm: 10; Value_Code: 10R0; Tolerance_%: 1; Power_W: 0.1; Value2: 0.1W; VDC_V: 75; TempCo: 100 ppm/C; SizeArea_mm2: 1.28; SizeX_mm: 1.6; SizeY_mm: 0.8; EIA_Code: E96; U/M: EA; AEC Category: Q200; Green_Lifecycle: Active; Green_REACh: Passed
R109 = CMP-21571-0000-1: Res Metal Strip 2512 2.3MilliOhm 1% 5W ±75ppm/°C Molded T/R; Manufacturer: Bourns; AEC Grade: Grade 0; AEC Qualified: Yes; SizeZ_mm: 1.09mm
R110 = CRCW12065R11FKEA: RES, 5.11, 1%, 0.25 W, 1206; Manufacturer: Vishay-Dale; CompType: Resistor; Value: 5.11; Value_Code: 5R11; Tolerance_%: 1; Power_W: 0.25; Value2: 0.25W; VDC_V: 200; TempCo: 100 ppm/C; SizeArea_mm2: 5.12; SizeX_mm: 3.2; SizeY_mm: 1.6; SizeZ_mm: 1.35; EIA_Code: E96; U/M: EA; AEC Category: Q200
R113 = CMP-0092403-1: RES 0.0025 OHM 1% 5W 3921; Manufacturer: Vishay; AEC Grade: Grade 0; SizeZ_mm: 0.081inch; TempCo: 350ppm/°C; AEC Qualified: Yes
R114 R119 = CMP-0026827-3: RES, 10, 5%, 0.063 W, AEC-Q200 Grade 0, 0402; Manufacturer: Vishay-Dale; Power_W: 63mW; TempCo: 200 ppm/C; Value_Code: 10R0; Value: 10; EIA_Code: E24; SizeX_mm: 1; SizeY_mm: 0.5; SizeZ_mm: 0.6; Value2: 0.063W; AEC Qualified: Y; VDC_V: 50V; AEC Category: Q200; AEC Grade: 0
R117 = CMP-0026822-3: RES, 0, 5%, 0.063 W, AEC-Q200 Grade 0, 0402; Manufacturer: Vishay-Dale; Power_W: 63mW; TempCo: 200 ppm/C; Value_Code: 0000; Value: 0; EIA_Code: E24; SizeX_mm: 1; SizeY_mm: 0.5; SizeZ_mm: 0.6; Value2: 0.063W; AEC Qualified: Y; VDC_V: 50V; AEC Category: Q200
R118 = CMP-0026404-1: RES, 49.9, 1%, 0.063 W, 0402; Manufacturer: Vishay-Dale; Power_W: 63mW; TempCo: 100 ppm/C; Value_Code: 49R9; U/M: EA; Value: 49.9; EIA_Code: E96; SizeX_mm: 1; SizeY_mm: 0.5; SizeZ_mm: 0.6; Value2: 0.063W; VDC_V: 50V; AEC Category: Q200
R121 = CMP-0026403-2: RES, 49.9 k, 1%, 0.063 W, AEC-Q200 Grade 0, 0402; Manufacturer: Vishay-Dale; Power_W: 63mW; TempCo: 100 ppm/C; Value_Code: 49k9; Value: 49.9k; EIA_Code: E96; SizeX_mm: 1; SizeY_mm: 0.5; SizeZ_mm: 0.6; Value2: 0.063W; AEC Qualified: Y; VDC_V: 50V; AEC Category: Q200; AEC Grade: 0
R122 = CMP-0026728-1: RES, 220 k, 1%, 0.0625 W, 0402; Manufacturer: Yageo America; Power_W: 62.5mW; TempCo: 100 ppm/C; U/M: EA; Value: 220k; SizeX_mm: 1; SizeY_mm: 0.5; SizeZ_mm: 0.6; AEC Qualified: N; VDC_V: 50V; AEC Category: Q200
R123 R126 = CMP-0078244-2: RES, 30.0 k, 1%, 0.063 W, AEC-Q200 Grade 0, 0402; Manufacturer: Vishay-Dale; Power_W: 63mW; Green_Lifecycle: Active; TempCo: 100 ppm/C; Value_Code: 30k0; Green_REACh: Passed; Value: 30.0k; Res_ohm: 30k; SizeX_mm: 1; SizeY_mm: 0.5; SizeZ_mm: 0.6; Value2: 0.063W; AEC Qualified: Y; VDC_V: 50V; AEC Grade: 0; AEC Category: Q200
R132 = CRCW0603200RFKEA: RES, 200 ohm, 1%, 0.1W, 0603; Manufacturer: Vishay-Dale; CompType: Resistor; Value_Code: 200R; Tolerance_%: 1; Power_W: 0.1; VDC_V: 75; TempCo: 100 ppm/C; EIA_Code: E96; U/M: EA
R134 R136 = CRCW04021K00JNED: RES, 1.0k ohm, 5%, 0.063W, 0402; Manufacturer: Vishay-Dale; CompType: Resistor; Res_ohm: 1000; Value_Code: 1k00; Tolerance_%: 5; Power_W: 0.063; VDC_V: 50; TempCo: 200 ppm/C; EIA_Code: E24; U/M: EA
R137 R139 R144 = CRCW04020000Z0ED: RES, 0, 5%, 0.063 W, 0402; Manufacturer: Vishay-Dale; CompType: Resistor; Value: 0; Value_Code: 0000; Tolerance_%: 5; Power_W: 0.063; Value2: 0.063W; VDC_V: 50; TempCo: 200 ppm/C; SizeArea_mm2: 0.5; SizeX_mm: 1; SizeZ_mm: 0.6; EIA_Code: E24; U/M: EA; AEC Category: Q200; Green_Lifecycle: Active; Green_REACh: Passed
R143 R147 = CRCW06030000Z0EA: RES, 0, 5%, 0.1 W, 0603; Manufacturer: Vishay-Dale; CompType: Resistor; Value: 0; Value_Code: 0000; Tolerance_%: 5; Power_W: 0.1; Value2: 0.1W; VDC_V: 75; TempCo: 200 ppm/C; EIA_Code: E24; U/M: EA; AEC Category: Q200
R145 = CRCW060310R0JNEAHP: RES, 10, 5%, 0.25 W, 0603; Manufacturer: Vishay-Dale; CompType: Resistor; Value: 10; Value_Code: 10R0; Tolerance_%: 5; Power_W: 0.25; Value2: 0.25W; VDC_V: 75; TempCo: 200 ppm/C; EIA_Code: E24; U/M: EA
R150-R158 = CRCW1206330KJNEA: RES, 330 k, 5%, 0.25 W, 1206; Manufacturer: Vishay-Dale; CompType: Resistor; Value: 330k; Res_ohm: 330000; Tolerance_%: 5; Power_W: 0.25; Value2: 0.25W; VDC_V: 200; TempCo: 200 ppm/C; SizeArea_mm2: 5.12; SizeX_mm: 3.2; SizeY_mm: 1.6; SizeZ_mm: 1.35; EIA_Code: E24; U/M: EA; AEC Category: Q200
RT100 = B59751B0120A070: Thermistor PTC, 50 ohm, 25%, D12.5xH16.5mm; Manufacturer: TDK; CompType: ThermistorNTC; Value: 50 ohm; Tolerance_%: 25; TaMin_C: -40; TaMax_C: 125; U/M: EA
RV150 = S10K275E2: Varistor 275V RMS 10MM Radial, TH; Manufacturer: EPCOS Inc; SymbolCreator: a0412235
TP101-TP106 = 0312-0-15-15-34-27-10-0: Pin Receptacle, .032-.046" .075" Dia, Gold, TH; Manufacturer: Mill-Max; Gender: Female
U100 = CMP-0097984-1: Part Number: TMCS1133B1QDVGR; Manufacturer: Texas Instruments; Standoff Height: 0.1mm; SizeZ_mm: 2.65mm
U101 = CMP-0013005-2: 620-V High-Side Low-Side Gate Driver with 2.5A Peak Output and RobustDrive, D0008A (SOIC-8); Manufacturer: Texas Instruments; SizeX_mm: 4.9; SizeY_mm: 6.2; CompType: IC; SizeZ_mm: 1.75; SizeArea_mm2: 30.38; SizeAreaWB_mm2: 56.58; U/M: EA
U102 = CMP-0077646-2: 4-A, 6-A, 3.0-kVRMS Isolated Dual-Channel Gate Driver, D0016B (SOIC-16); Alternate Manufacturer: Texas Instruments; SizeAreaWB_mm2: 95.2; SizeZ_mm: 1.75; SizeX_mm: 6.0; SizeY_mm: 9.9; SizeArea_mm2: 59.4; CompType: IC; AEC Qualified: N; AEC Category: Q200; Rating: Catalog
U104 = CMP-0085668-1: Small Reinforced Isolated Modulator With +/-50mV Input and CMOS Interface, DWV0008A (SOIC-8); Manufacturer: Texas Instruments; Alternate PartNumber: AMC1306M05DWVR; SizeY_mm: 5.85; Rating: Catalog; CompType: IC; SizeZ_mm: 2.8; AEC Qualified: N; SizeArea_mm2: 67.275; AEC Category: Q200; SizeAreaWB_mm2: 105.975; SizeX_mm: 11.5
U105 = TLV71333PQDBVRQ1: Capacitor-Free, 150-mA, Low-Dropout Regulator with Foldback Current Limit for Portable Devices, DBV0005A; Manufacturer: Texas Instruments; SymbolCreator: Altium; SizeArea_mm2: 8.12; SizeAreaWB_mm2: 14.82; SizeX_mm: 2.8; SizeY_mm: 2.9; SizeZ_mm: 1.45; CompType: IC; U/M: EA
U106 = UCC27511DBVR: Single-Channel High-Speed Low-Side Gate Driver (with 4-A Peak Source and 8-A Peak Sink), DBV0006A; Alternate PartNumber: UCC27511DBVT; Manufacturer: Texas Instruments; SymbolCreator: a0411947; CompType: IC; U/M: EA
U107 = CMP-0097277-1: 3V to 16 V Input, 3-A Synchronous Step-Down Voltage Regulator Module, QFN-FCMOD7; Manufacturer: Texas Instruments; Nominal Supply Current: 120-400uA; SizeZ_mm: 2.1mm; AEC Qualified: No; Output Type: AdjustableProgrammable; Switching Topology: Buck; AEC Grade: NA; Standoff Height: 0mm; Max Supply Voltage: 16V; Number Of Outputs: 1; Switching Frequency: 1400/2000kHz; TJmax_C: +125°C; Max Duty Cycle: 98%; Output Voltage: 0.6-7V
